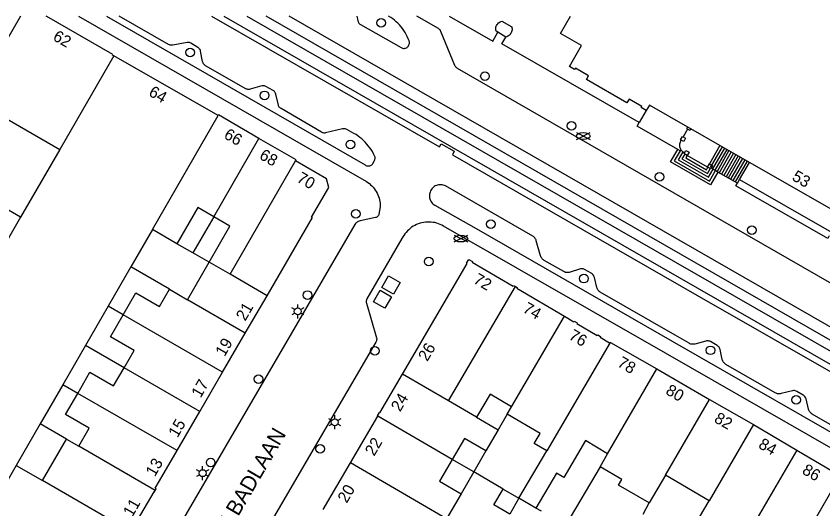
# Model space of a CAD drawing. Extents: x 122462 to 123306, y 485548 to 486417.
# Drawn here: x 122924.9 to 123029.5, y 486353 to 486417 of the extents above; entities that cross this region are included whole.
import ezdxf

# ---------------------------------------------------------------- set-up
doc = ezdxf.new("R2010")
doc.units = 0
for name, color, linetype in [('B-WE-IE-MEUBILAIR_WEGMEUBILAIR_VERKEERSBORD-S', 7, 'Continuous'), ('Level 1', 7, 'Continuous'), ('Level 17', 7, 'Continuous'), ('Level 19', 7, 'Continuous'), ('Level 2', 7, 'Continuous'), ('Level 21', 7, 'Continuous'), ('Level 22', 7, 'Continuous'), ('Level 30', 7, 'Continuous'), ('Level 31', 7, 'Continuous'), ('Level 33', 7, 'Continuous'), ('Level 37', 7, 'Continuous'), ('Level 4', 7, 'Continuous'), ('Level 42', 7, 'Continuous'), ('Level 50', 7, 'Continuous'), ('Level 52', 7, 'Continuous'), ('Level 53', 7, 'Continuous'), ('N werkgrens', 7, 'Continuous'), ('N-WE-GR-BOOM_DOORWORTELBARE RUIMTE-G', 7, 'Continuous')]:
    doc.layers.add(name, color=color, linetype=linetype)

msp = doc.modelspace()

# ---------------------------------------------------------------- linework, layer by layer
at = {"layer": 'Level 1'}
for p, q in [((122951.1, 486404.09), (122937.54, 486411.82)), ((123012.42, 486402.33), (123012, 486402.57)), ((123016.17, 486400.18), (123012.42, 486402.33)), ((123019.99, 486397.99), (123016.17, 486400.18)), ((122930.54, 486399.67), (122925.46, 486390.88)), ((123031.91, 486391.17), (123019.99, 486397.99)), ((122942.56, 486389.28), (122939.75, 486384.42)), ((122945.75, 486387.43), (122942.56, 486389.28)), ((122939.75, 486384.42), (122936.82, 486379.34)), ((122947.1, 486380.18), (122949.91, 486385.04)), ((122944.76, 486381.53), (122947.1, 486380.18)), ((122954.61, 486375.84), (122957.43, 486380.7)), ((122936.82, 486379.34), (122933.88, 486374.25)), ((122951.67, 486370.77), (122954.61, 486375.84)), ((122933.88, 486374.25), (122930.94, 486369.15)), ((122948.72, 486365.69), (122951.67, 486370.77)), ((123007.99, 486371.2), (123014.83, 486367.25)), ((122930.94, 486369.15), (122928, 486364.06)), ((123014.83, 486367.25), (123020.51, 486363.97)), ((122945.76, 486360.6), (122948.72, 486365.69)), ((122988.57, 486365.33), (122989.13, 486366.29)), ((122968.26, 486359.01), (122971.8, 486365.07)), ((122984.61, 486364.92), (122987.42, 486363.29)), ((122928, 486364.06), (122924.9, 486358.68)), ((123020.51, 486363.97), (123026.14, 486360.65)), ((122987.42, 486363.29), (122985.83, 486360.56)), ((122928.3, 486356.72), (122931.4, 486362.1)), ((122931.4, 486362.1), (122933.01, 486361.17)), ((122990.11, 486354.42), (122993.72, 486360.59)), ((123000.62, 486358.52), (123001.6, 486360.2)), ((122924.9, 486358.68), (122928.3, 486356.72)), ((122964.73, 486352.95), (122968.26, 486359.01)), ((123009.1, 486357.41), (123007, 486353.81)), ((123014.76, 486354.1), (123009.1, 486357.41)), ((122982.6, 486355.01), (122980.71, 486351.77)), ((122992.3, 486353.14), (122990.11, 486354.42)), ((123013.52, 486351.98), (123014.76, 486354.1))]:
    msp.add_line(p, q, dxfattribs=at)
for points in [[(122925.45, 486416.96), (122919.24, 486406.18), (122930.54, 486399.67)], [(122937.54, 486411.82), (122937.4, 486411.9), (122937.44, 486411.97), (122928.88, 486416.9), (122928.78, 486416.96)], [(123006.61, 486404.71), (123005.94, 486405.09), (123006.03, 486405.25), (123004.39, 486406.19), (123004.11, 486405.71), (122998.86, 486408.73), (122999.14, 486409.21), (122997.42, 486410.19), (122997.33, 486410.04), (122996.66, 486410.42), (122998.23, 486413.16), (122995.51, 486414.72), (122996.79, 486416.96)], [(123012, 486402.57), (123007.02, 486405.42), (123006.61, 486404.71)], [(122956.38, 486401.1), (122951.13, 486404.14), (122951.1, 486404.09)], [(122961.12, 486398.18), (122961.19, 486398.31), (122956.38, 486401.1)], [(122957.43, 486380.7), (122963.31, 486390.82), (122963.2, 486390.88), (122965.44, 486394.74), (122965.16, 486395.84), (122961.12, 486398.18)], [(122925.46, 486390.88), (122914.11, 486397.44), (122900.28, 486373.5)], [(122950.52, 486390.94), (122948.46, 486392.13), (122945.75, 486387.43)], [(122949.91, 486385.04), (122952.62, 486389.73), (122950.52, 486390.94)], [(122974.99, 486370.52), (122983.39, 486384.88), (122983.31, 486384.93), (122983.59, 486385.41), (122984.08, 486385.13), (122984.03, 486385.04), (122989.35, 486381.95), (122989.4, 486382.03), (122989.64, 486381.89)], [(122938.75, 486378.22), (122940.4, 486381.08), (122943.48, 486379.31), (122944.76, 486381.53)], [(122989.64, 486381.89), (122989.88, 486381.75), (122989.84, 486381.67), (122996, 486378.03)], [(122938.89, 486371.36), (122940.18, 486373.59), (122937.11, 486375.37), (122938.75, 486378.22)], [(122996, 486378.03), (122997.24, 486377.29), (122997.29, 486377.38), (122997.66, 486377.17), (122997.6, 486377.07), (123000.26, 486375.53), (123000.32, 486375.62), (123000.68, 486375.41), (123000.62, 486375.31), (123001.85, 486374.6), (123001.93, 486374.62)], [(123001.93, 486374.62), (123002, 486374.64), (123007.99, 486371.2)], [(122932.87, 486368.03), (122934.45, 486370.76), (122937.52, 486368.99), (122938.89, 486371.36)], [(122971.8, 486365.07), (122971.74, 486365.1), (122972.01, 486365.56), (122972.06, 486365.52), (122974.99, 486370.52)], [(122933.01, 486361.17), (122934.37, 486363.53), (122931.3, 486365.3), (122932.87, 486368.03)], [(122989.13, 486366.29), (122986.36, 486367.91), (122984.61, 486364.92)], [(122993.72, 486360.59), (122992.09, 486361.54), (122992.85, 486362.83), (122988.57, 486365.33)], [(122985.83, 486360.56), (122983.03, 486362.19), (122981.44, 486359.46)], [(123001.6, 486360.2), (122998.72, 486361.9), (122995.93, 486357.13), (122994.96, 486357.69), (122992.3, 486353.14)], [(122942.93, 486355.45), (122943.05, 486355.66), (122942.93, 486355.73), (122943.48, 486356.68), (122945.76, 486360.6)], [(123026.14, 486360.65), (123031.5, 486357.49), (123031.55, 486357.58), (123031.83, 486357.42)], [(122981.44, 486359.46), (122979.8, 486356.64), (122982.6, 486355.01)], [(123007, 486353.81), (123003.04, 486356.12), (123003.47, 486356.86), (123000.62, 486358.52)], [(122939.78, 486350.09), (122942.77, 486355.26), (122942.81, 486355.23), (122942.93, 486355.45)]]:
    msp.add_lwpolyline(points, dxfattribs=at)
at = {"layer": 'Level 17'}
for points in [[(122932.97, 486416.96), (122970.32, 486395.49), (122970.51, 486395.37), (122970.7, 486395.23), (122970.87, 486395.08), (122971.04, 486394.93), (122971.2, 486394.76), (122971.34, 486394.58), (122971.47, 486394.4), (122971.6, 486394.2), (122971.71, 486394), (122971.8, 486393.79), (122971.89, 486393.58), (122971.96, 486393.36), (122972.01, 486393.14), (122972.06, 486392.92), (122972.09, 486392.69), (122972.1, 486392.46), (122972.1, 486392.24), (122971.95, 486391.29), (122971.92, 486391.19), (122971.87, 486391.11), (122971.82, 486391.03), (122971.75, 486390.96), (122971.67, 486390.9), (122971.58, 486390.86), (122971.48, 486390.83), (122969.49, 486390.41), (122969.37, 486390.38), (122969.26, 486390.34), (122969.16, 486390.28), (122969.06, 486390.21), (122968.97, 486390.13), (122968.89, 486390.04), (122968.83, 486389.94), (122947.99, 486354.19), (122925.62, 486315.8)], [(122936.62, 486416.96), (122970.17, 486397.66), (122970.25, 486397.6), (122970.35, 486397.56), (122970.45, 486397.54), (122970.55, 486397.53)], [(122971.43, 486398.39), (122971.45, 486398.48), (122971.45, 486398.57), (122971.44, 486398.66), (122971.42, 486398.75), (122971.39, 486398.83), (122971.25, 486399.11), (122971.1, 486399.38), (122970.93, 486399.64), (122970.75, 486399.89), (122970.56, 486400.14), (122970.37, 486400.37), (122970.16, 486400.6), (122969.94, 486400.82), (122969.71, 486401.03), (122969.47, 486401.22), (122969.23, 486401.41), (122968.97, 486401.59), (122968.71, 486401.75), (122967.77, 486402.26), (122967.68, 486402.3), (122967.58, 486402.33), (122967.49, 486402.35), (122967.39, 486402.36), (122967.29, 486402.35), (122967.2, 486402.34), (122965.01, 486401.81), (122964.92, 486401.79), (122964.83, 486401.79), (122964.73, 486401.8), (122964.65, 486401.82), (122964.56, 486401.85), (122964.48, 486401.89), (122959.25, 486404.96), (122959.16, 486405.02), (122959.09, 486405.09), (122959.02, 486405.16), (122958.97, 486405.25), (122958.93, 486405.34), (122958.9, 486405.43), (122958.56, 486406.85), (122958.53, 486406.95), (122958.49, 486407.03), (122958.44, 486407.11), (122958.38, 486407.18), (122958.3, 486407.25), (122958.22, 486407.3), (122957.27, 486407.84), (122957.18, 486407.88), (122957.08, 486407.91), (122956.97, 486407.93), (122956.87, 486407.92), (122956.76, 486407.91), (122955.25, 486407.47), (122955.15, 486407.45), (122955.05, 486407.44), (122954.95, 486407.45), (122954.85, 486407.47), (122954.76, 486407.5), (122954.67, 486407.54), (122949.46, 486410.52), (122949.38, 486410.58), (122949.3, 486410.64), (122949.24, 486410.71), (122949.18, 486410.79), (122949.13, 486410.88), (122949.09, 486410.97), (122949.07, 486411.06), (122948.8, 486412.42), (122948.78, 486412.52), (122948.74, 486412.61), (122948.69, 486412.69), (122948.62, 486412.77), (122948.55, 486412.84), (122948.47, 486412.89), (122947.54, 486413.44), (122947.46, 486413.48), (122947.36, 486413.52), (122947.26, 486413.53), (122947.16, 486413.54), (122947.06, 486413.53), (122945.21, 486413.19), (122945.09, 486413.18), (122944.98, 486413.18), (122944.87, 486413.2), (122944.76, 486413.24), (122944.66, 486413.29), (122938.27, 486416.96)], [(122950.23, 486416.96), (122979.78, 486400.01), (122980.01, 486400.41), (122981.72, 486399.43), (122981.48, 486398.96), (123013.2, 486380.78), (123042.88, 486363.77)], [(122969.08, 486416.96), (122969.22, 486416.37), (122969.23, 486416.28), (122969.26, 486416.2), (122969.3, 486416.12), (122969.35, 486416.05), (122969.41, 486415.98), (122969.48, 486415.93), (122969.55, 486415.88), (122974.82, 486412.87), (122974.91, 486412.83), (122975.01, 486412.8), (122975.11, 486412.78), (122975.21, 486412.78)], [(122975.21, 486412.78), (122975.31, 486412.79), (122975.41, 486412.82), (122975.5, 486412.86), (122975.59, 486412.91), (122975.67, 486412.97), (122975.73, 486413.04), (122975.79, 486413.12), (122975.84, 486413.22), (122975.87, 486413.31), (122975.89, 486413.41), (122975.9, 486413.51), (122975.89, 486413.61), (122975.87, 486413.71), (122975.85, 486413.74), (122975.74, 486414.03), (122975.62, 486414.3), (122975.49, 486414.57), (122975.34, 486414.84), (122975.17, 486415.09), (122975, 486415.34), (122974.81, 486415.58), (122974.62, 486415.81), (122974.41, 486416.03), (122974.19, 486416.24), (122973.96, 486416.43), (122973.73, 486416.62), (122973.48, 486416.8), (122973.2, 486416.96)], [(123071.25, 486358.26), (123070.51, 486358.82), (123069.77, 486359.37), (123069.02, 486359.91), (123068.26, 486360.44), (123067.5, 486360.95), (123066.72, 486361.46), (123065.94, 486361.95), (123061.62, 486364.46), (123017.98, 486389.56), (122982.14, 486410.18), (122982.05, 486410.24), (122981.97, 486410.31), (122981.9, 486410.39), (122981.84, 486410.47), (122981.8, 486410.57), (122979.99, 486414.97), (122979.94, 486415.07), (122979.88, 486415.16), (122979.81, 486415.23), (122979.73, 486415.3), (122979.65, 486415.36), (122976.86, 486416.96)], [(122981.06, 486416.96), (122986.7, 486413.72), (122987.36, 486414.86)], [(122970.55, 486397.53), (122970.65, 486397.53), (122970.76, 486397.55), (122970.85, 486397.58), (122970.94, 486397.63), (122971.03, 486397.69), (122971.1, 486397.76), (122971.17, 486397.84), (122971.37, 486398.22), (122971.4, 486398.3), (122971.43, 486398.39)], [(123000.41, 486381.38), (123000.35, 486381.47), (123000.3, 486381.56), (123000.26, 486381.66), (123000.23, 486381.77), (122999.91, 486383.05), (122999.88, 486383.16), (122999.84, 486383.25), (122999.78, 486383.34), (122999.71, 486383.42), (122999.63, 486383.5), (122999.54, 486383.56), (122998.63, 486384.08), (122998.54, 486384.13), (122998.45, 486384.16), (122998.36, 486384.18), (122998.26, 486384.19), (122998.16, 486384.19), (122998.07, 486384.18), (122997.97, 486384.15), (122996.76, 486383.74), (122996.64, 486383.71), (122996.52, 486383.69), (122996.4, 486383.69), (122996.28, 486383.7), (122996.16, 486383.72), (122996.05, 486383.76), (122995.94, 486383.82), (122993.38, 486385.27), (122993.29, 486385.33), (122993.2, 486385.4), (122993.12, 486385.48), (122993.06, 486385.57), (122993, 486385.66), (122992.95, 486385.76), (122992.92, 486385.87), (122992.36, 486387.83), (122992.32, 486387.94), (122992.27, 486388.04), (122992.21, 486388.13), (122992.15, 486388.22), (122992.07, 486388.3), (122991.98, 486388.37), (122991.89, 486388.43), (122980.57, 486394.94), (122980.43, 486395), (122980.29, 486395.05), (122980.14, 486395.08), (122979.99, 486395.09), (122979.84, 486395.09), (122979.69, 486395.07), (122979.54, 486395.04), (122979.4, 486394.99), (122979.26, 486394.93), (122979.13, 486394.85), (122979.01, 486394.76), (122978.9, 486394.65), (122978.8, 486394.54), (122978.71, 486394.42), (122978.64, 486394.28), (122978.58, 486394.14), (122978.54, 486394), (122978.51, 486393.85), (122978.5, 486393.7), (122978.5, 486393.55), (122978.52, 486393.4), (122978.55, 486393.25), (122978.6, 486393.11), (122978.67, 486392.97), (122978.75, 486392.84), (122978.84, 486392.72), (122978.94, 486392.61), (122979.06, 486392.51), (122979.18, 486392.43), (122984.55, 486389.4), (123009.96, 486374.82), (123036.85, 486359.4)], [(123043.86, 486353.31), (123009.1, 486373.24), (122980.33, 486389.72), (122980.12, 486389.84), (122979.9, 486389.94), (122979.67, 486390.03), (122979.44, 486390.11), (122979.21, 486390.17), (122978.97, 486390.21), (122978.72, 486390.24), (122978.48, 486390.25), (122978.24, 486390.25), (122977.99, 486390.24), (122977.75, 486390.2), (122977.51, 486390.16), (122977.28, 486390.09), (122977.05, 486390.02), (122976.82, 486389.92), (122976.6, 486389.82), (122976.39, 486389.7), (122976.19, 486389.57), (122975.99, 486389.42), (122975.81, 486389.26), (122975.63, 486389.09), (122975.47, 486388.91), (122975.32, 486388.72), (122975.18, 486388.52), (122975.05, 486388.32), (122974.93, 486388.1), (122970.39, 486380.31), (122970.35, 486380.21), (122970.32, 486380.12), (122970.3, 486380.02), (122970.3, 486379.92), (122970.31, 486379.82), (122970.33, 486379.72), (122971.64, 486375.23), (122971.66, 486375.14), (122971.66, 486375.04), (122971.64, 486374.94), (122971.62, 486374.84), (122971.58, 486374.75)], [(123035.75, 486360.98), (123028.13, 486365.35), (123028.03, 486365.42), (123027.95, 486365.49), (123027.87, 486365.58), (123027.8, 486365.67), (123027.74, 486365.77), (123027.69, 486365.87), (123027.66, 486365.99), (123027.34, 486367.3), (123027.3, 486367.41), (123027.26, 486367.5), (123027.2, 486367.6), (123027.13, 486367.68), (123027.05, 486367.75), (123026.96, 486367.81), (123026.15, 486368.27), (123026.05, 486368.32), (123025.95, 486368.36), (123025.83, 486368.38), (123025.72, 486368.38), (123025.61, 486368.37), (123024.1, 486367.99), (123023.99, 486367.97), (123023.88, 486367.97), (123023.77, 486367.97), (123023.66, 486367.98), (123023.56, 486368.01), (123023.46, 486368.05), (123023.36, 486368.1), (123016.95, 486371.78), (123016.85, 486371.85), (123016.75, 486371.93), (123016.67, 486372.01), (123016.6, 486372.11), (123016.54, 486372.22), (123016.5, 486372.33), (123016.47, 486372.44), (123016.2, 486373.71), (123016.17, 486373.81), (123016.12, 486373.92), (123016.07, 486374.01), (123015.99, 486374.1), (123015.91, 486374.17), (123015.82, 486374.23), (123014.95, 486374.74), (123014.85, 486374.79), (123014.75, 486374.82), (123014.65, 486374.84), (123014.54, 486374.85), (123014.43, 486374.84), (123014.33, 486374.82), (123012.93, 486374.42), (123012.82, 486374.4), (123012.72, 486374.39), (123012.61, 486374.39), (123012.5, 486374.41), (123012.39, 486374.43), (123012.29, 486374.47), (123012.2, 486374.52), (123010.37, 486375.57), (123000.65, 486381.16), (123000.56, 486381.23), (123000.48, 486381.3), (123000.41, 486381.38)], [(122971.58, 486374.75), (122971.54, 486374.67), (122967.76, 486368.22), (122956.77, 486349.34)]]:
    msp.add_lwpolyline(points, dxfattribs=at)
at = {"layer": 'Level 19'}
for p, q in [((122950.52, 486390.94), (122947.81, 486386.25)), ((122947.81, 486386.25), (122945.75, 486387.43)), ((122949.91, 486385.04), (122947.81, 486386.25)), ((122944.76, 486381.53), (122939.75, 486384.42)), ((122938.75, 486378.22), (122936.82, 486379.34)), ((122938.89, 486371.36), (122933.88, 486374.25)), ((122932.87, 486368.03), (122930.94, 486369.15)), ((122988.57, 486365.33), (122987.42, 486363.29)), ((122931.4, 486362.1), (122928, 486364.06)), ((122985.83, 486360.56), (122984.24, 486357.83)), ((122984.24, 486357.83), (122981.44, 486359.46)), ((123000.62, 486358.52), (122996.2, 486350.97)), ((122984.24, 486357.83), (122982.6, 486355.01)), ((122988.06, 486355.61), (122984.24, 486357.83)), ((122993.01, 486352.75), (122992.3, 486353.14)), ((123006.2, 486352.37), (123007, 486353.81))]:
    msp.add_line(p, q, dxfattribs=at)
at = {"layer": 'Level 2'}
msp.add_line((122988.06, 486355.61), (122990.11, 486354.42), dxfattribs=at)
msp.add_lwpolyline([(122990.11, 486354.42), (122988.92, 486352.38), (122986.87, 486353.57), (122988.06, 486355.61)], dxfattribs=at)
at = {"layer": 'Level 21'}
for p, q in [((123014.56, 486397.37), (123014.81, 486397.8)), ((123018.44, 486395.29), (123018.72, 486395.78)), ((123018.72, 486395.78), (123030.64, 486388.95))]:
    msp.add_line(p, q, dxfattribs=at)
for points in [[(123011.99, 486402.31), (123011.88, 486402.37), (123012, 486402.57)], [(123012.42, 486402.33), (123012.31, 486402.13), (123011.99, 486402.31)], [(123011.16, 486400.87), (123011.06, 486400.93), (123011.3, 486401.35), (123011.4, 486401.29)], [(123011.4, 486401.29), (123011.72, 486401.11), (123011.48, 486400.68), (123011.16, 486400.87)], [(123011.93, 486398.88), (123011.5, 486399.13), (123011.56, 486399.23)], [(123011.56, 486399.23), (123011.74, 486399.55), (123012.17, 486399.31), (123011.93, 486398.88)], [(123015.04, 486397.24), (123014.98, 486397.14), (123014.56, 486397.37)], [(123014.81, 486397.8), (123015.22, 486397.56), (123015.04, 486397.24)], [(123030.36, 486388.46), (123030.17, 486388.13), (123020.29, 486393.79), (123018.25, 486394.96), (123018.44, 486395.29)]]:
    msp.add_lwpolyline(points, dxfattribs=at)
at = {"layer": 'Level 22'}
for p, q in [((123011.99, 486402.31), (123011.4, 486401.29)), ((123018.44, 486395.29), (123015.91, 486396.74))]:
    msp.add_line(p, q, dxfattribs=at)
for points in [[(123011.11, 486399.66), (123011.06, 486399.77), (123011.01, 486399.89), (123010.98, 486400.02), (123010.96, 486400.14), (123010.96, 486400.27), (123010.97, 486400.4), (123011, 486400.52), (123011.04, 486400.64), (123011.09, 486400.76), (123011.16, 486400.87)], [(123011.56, 486399.23), (123011.54, 486399.24), (123011.45, 486399.3), (123011.36, 486399.37), (123011.27, 486399.46), (123011.19, 486399.55), (123011.11, 486399.66)], [(123015.91, 486396.74), (123015.6, 486396.92), (123015.04, 486397.24)]]:
    msp.add_lwpolyline(points, dxfattribs=at)
at = {"layer": 'Level 30'}
for p, q in [((123016.17, 486400.18), (123014.81, 486397.8)), ((123014.56, 486397.37), (123011.93, 486398.88)), ((123018.72, 486395.78), (123019.99, 486397.99))]:
    msp.add_line(p, q, dxfattribs=at)
at = {"layer": 'Level 31'}
msp.add_line((123011.01, 486399.49), (123011.11, 486399.66), dxfattribs=at)
msp.add_lwpolyline([(123015.91, 486396.74), (123014.96, 486395.07), (123009.77, 486398.04), (123010.7, 486399.67)], dxfattribs=at)
at = {"layer": 'Level 33'}
for p, q in [((123016.47, 486400.01), (123014.92, 486397.31)), ((123016.76, 486399.85), (123015.21, 486397.14)), ((123017.05, 486399.68), (123015.5, 486396.97)), ((123017.35, 486399.51), (123015.8, 486396.8)), ((123017.64, 486399.34), (123016.09, 486396.64)), ((123017.93, 486399.17), (123016.38, 486396.47)), ((123018.23, 486399), (123016.68, 486396.3)), ((123018.52, 486398.84), (123016.97, 486396.13)), ((123018.81, 486398.67), (123017.26, 486395.96)), ((123019.11, 486398.5), (123017.56, 486395.79)), ((123019.4, 486398.33), (123017.85, 486395.62)), ((123019.7, 486398.16), (123018.15, 486395.46))]:
    msp.add_line(p, q, dxfattribs=at)
for points in [[(123011.01, 486399.49), (123010.26, 486398.18), (123014.83, 486395.56), (123015.6, 486396.92)], [(123011.36, 486399.37), (123010.76, 486398.31), (123014.69, 486396.05), (123015.29, 486397.09)], [(123011.61, 486399.07), (123011.25, 486398.44), (123014.56, 486396.55), (123014.92, 486397.17)], [(123011.93, 486398.88), (123011.74, 486398.58), (123014.43, 486397.04), (123014.61, 486397.35)]]:
    msp.add_lwpolyline(points, dxfattribs=at)
at = {"layer": 'Level 37'}
for points in [[(122951.82, 486416.96), (123052.68, 486359.06)], [(122954.79, 486416.96), (123053.42, 486360.34)], [(123054.66, 486361.05), (122957.33, 486416.96)], [(123055.4, 486362.33), (122960.3, 486416.96)]]:
    msp.add_lwpolyline(points, dxfattribs=at)
at = {"layer": 'Level 4'}
for p, q in [((122937.54, 486411.82), (122930.54, 486399.67)), ((122942.56, 486389.28), (122951.1, 486404.09)), ((122950.52, 486390.94), (122956.38, 486401.1)), ((122952.63, 486383.47), (122961.12, 486398.18)), ((122925.46, 486390.88), (122920.28, 486381.92)), ((122952.63, 486383.47), (122949.91, 486385.04)), ((122957.43, 486380.7), (122952.63, 486383.47)), ((122980.95, 486367.05), (122989.64, 486381.89)), ((122954.61, 486375.84), (122947.1, 486380.18)), ((122951.67, 486370.77), (122938.75, 486378.22)), ((122989.13, 486366.29), (122996, 486378.03)), ((123001.93, 486374.62), (122993.72, 486360.59)), ((122948.72, 486365.69), (122938.89, 486371.36)), ((123001.6, 486360.2), (123007.99, 486371.2)), ((122980.95, 486367.05), (122974.99, 486370.52)), ((122945.76, 486360.6), (122932.87, 486368.03)), ((122984.61, 486364.92), (122980.95, 486367.05)), ((123009.1, 486357.41), (123014.83, 486367.25)), ((122981.44, 486359.46), (122971.8, 486365.07)), ((123020.51, 486363.97), (123014.76, 486354.1)), ((122942.93, 486355.45), (122933.01, 486361.17)), ((123026.14, 486360.65), (123020.41, 486350.81)), ((122924.9, 486358.68), (122918.91, 486348.31)), ((122980.71, 486351.77), (122968.26, 486359.01)), ((123031.83, 486357.42), (123026.06, 486347.52)), ((122939.78, 486350.09), (122928.3, 486356.72))]:
    msp.add_line(p, q, dxfattribs=at)
at = {"layer": 'Level 42'}
for points in [[(122973.82, 486380.89), (122972.3, 486381.77), (122973.18, 486383.28), (122974.7, 486382.41), (122973.82, 486380.89)], [(122972.73, 486379.06), (122971.24, 486379.92), (122972.09, 486381.41), (122973.59, 486380.56), (122972.73, 486379.06)]]:
    msp.add_lwpolyline(points, dxfattribs=at)
at = {"layer": 'Level 50'}
for p, q in [((122961.03, 486378.89), (122960.64, 486379.11)), ((122961.42, 486379.11), (122961.42, 486379.56)), ((122962.2, 486379.11), (122961.81, 486378.89)), ((122961.03, 486378.44), (122960.64, 486378.21)), ((122961.42, 486377.76), (122961.42, 486378.21)), ((122962.2, 486378.21), (122961.81, 486378.44)), ((122965.83, 486364.5), (122965.44, 486364.73)), ((122966.22, 486364.73), (122966.22, 486365.18)), ((122967, 486364.73), (122966.61, 486364.5)), ((122965.83, 486364.05), (122965.44, 486363.83)), ((122966.22, 486363.38), (122966.22, 486363.83)), ((122967, 486363.83), (122966.61, 486364.05)), ((122949.08, 486358.13), (122949.08, 486358.58)), ((122948.69, 486357.91), (122948.3, 486358.13)), ((122948.69, 486357.46), (122948.3, 486357.23)), ((122949.08, 486356.78), (122949.08, 486357.23)), ((122949.86, 486358.13), (122949.47, 486357.91)), ((122949.86, 486357.23), (122949.47, 486357.46))]:
    msp.add_line(p, q, dxfattribs=at)
for centre in [(122961.42, 486378.66), (122966.22, 486364.28), (122949.08, 486357.68)]:
    msp.add_circle(centre, 0.45, dxfattribs=at)
at = {"layer": 'Level 52'}
for p, q in [((122997.56, 486400.97), (122999.34, 486401.86)), ((122997.56, 486401.86), (122999.34, 486400.97)), ((122981.69, 486387.67), (122983.47, 486388.56)), ((122981.69, 486388.56), (122983.47, 486387.67))]:
    msp.add_line(p, q, dxfattribs=at)
for centre in [(122998.45, 486401.41), (122982.58, 486388.11)]:
    msp.add_ellipse(centre, major_axis=(0.89, 0), ratio=0.5, dxfattribs=at)
at = {"layer": 'Level 53'}
for centre in [(122972.24, 486416.1), (122947.46, 486412.25), (122985.7, 486409.18), (122957.12, 486406.68), (122996.93, 486402.72), (122968.24, 486400.32), (123008.35, 486396.1), (122968.95, 486391.32), (122986.45, 486389.97), (123020.31, 486389.19), (122978.4, 486385.14), (122998.54, 486382.91), (122962.69, 486380.78), (122971.42, 486373.53), (123014.95, 486373.61), (122956.33, 486369.88), (123026.06, 486367.18), (122964.31, 486360.82), (122950.12, 486359.06)]:
    msp.add_circle(centre, 0.56, dxfattribs=at)
at = {"layer": 'N werkgrens'}
for p, q in [((122988.41, 486414.25), (122987.36, 486414.86)), ((123006.61, 486404.71), (123005.72, 486403.16)), ((123011.01, 486399.49), (123010.7, 486399.67))]:
    msp.add_line(p, q, dxfattribs=at)
for points in [[(122987.36, 486414.86), (122987.13, 486415), (122987.1, 486415.12), (122987.1, 486415.25), (122987.1, 486415.38), (122987.12, 486415.51), (122987.16, 486415.64), (122987.21, 486415.76), (122987.28, 486415.87), (122987.36, 486415.97), (122987.45, 486416.07), (122987.55, 486416.15), (122987.66, 486416.22), (122987.77, 486416.28), (122987.9, 486416.32), (122989.18, 486415.58), (122989.2, 486415.45), (122989.21, 486415.32), (122989.21, 486415.19), (122989.19, 486415.06), (122989.15, 486414.93), (122989.1, 486414.81), (122989.03, 486414.7), (122988.95, 486414.59), (122988.86, 486414.5), (122988.76, 486414.42), (122988.65, 486414.35), (122988.53, 486414.29), (122988.41, 486414.25)], [(123005.72, 486403.16), (122987.89, 486413.37), (122988.41, 486414.25)], [(123010.7, 486399.67), (123005.45, 486402.68), (123005.72, 486403.16)]]:
    msp.add_lwpolyline(points, dxfattribs=at)

# ---------------------------------------------------------------- texts
at = {"layer": 'B-WE-IE-MEUBILAIR_WEGMEUBILAIR_VERKEERSBORD-S'}
for s, rotation, p in [('62', 330.0443, (122929.54, 486413.93)), ('64', 330.0443, (122941.96, 486406.72)), ('66', 330.0443, (122951.72, 486401.2)), ('68', 330.0443, (122956.32, 486398.53)), ('53', 330.2049, (123025.41, 486395.76)), ('70', 330.0443, (122961.17, 486395.55)), ('72', 330.0298, (122984.08, 486382.41)), ('21', 59.939, (122954.6, 486377.32)), ('74', 330.0298, (122990.5, 486378.65)), ('76', 330.0298, (122996.45, 486375.14)), ('19', 59.939, (122951.92, 486372.7)), ('26', 59.6549, (122978.22, 486372.08)), ('78', 330.0298, (123002.76, 486371.61)), ('17', 59.939, (122948.81, 486367.34)), ('80', 330.0298, (123009.02, 486368.01)), ('24', 59.5127, (122974.69, 486365.55)), ('82', 330.0298, (123015.31, 486364.38)), ('15', 59.939, (122945.82, 486362.19)), ('22', 59.5127, (122971.32, 486359.8)), ('84', 330.0298, (123021.05, 486361.03)), ('13', 59.939, (122942.88, 486357.13)), ('86', 330.0298, (123026.72, 486357.69)), ('20', 59.5127, (122967.77, 486353.7)), ('11', 59.939, (122939.95, 486351.89))]:
    msp.add_text(s, height=1.5, rotation=rotation, dxfattribs=at).set_placement(p)
at = {"layer": 'N-WE-GR-BOOM_DOORWORTELBARE RUIMTE-G'}
msp.add_text('PLANTAGE BADLAAN', height=2, rotation=59.7889, dxfattribs=at).set_placement((122946.14, 486339.02))

doc.saveas('drawing.dxf')
